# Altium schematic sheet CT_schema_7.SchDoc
size 218 x 258 mm
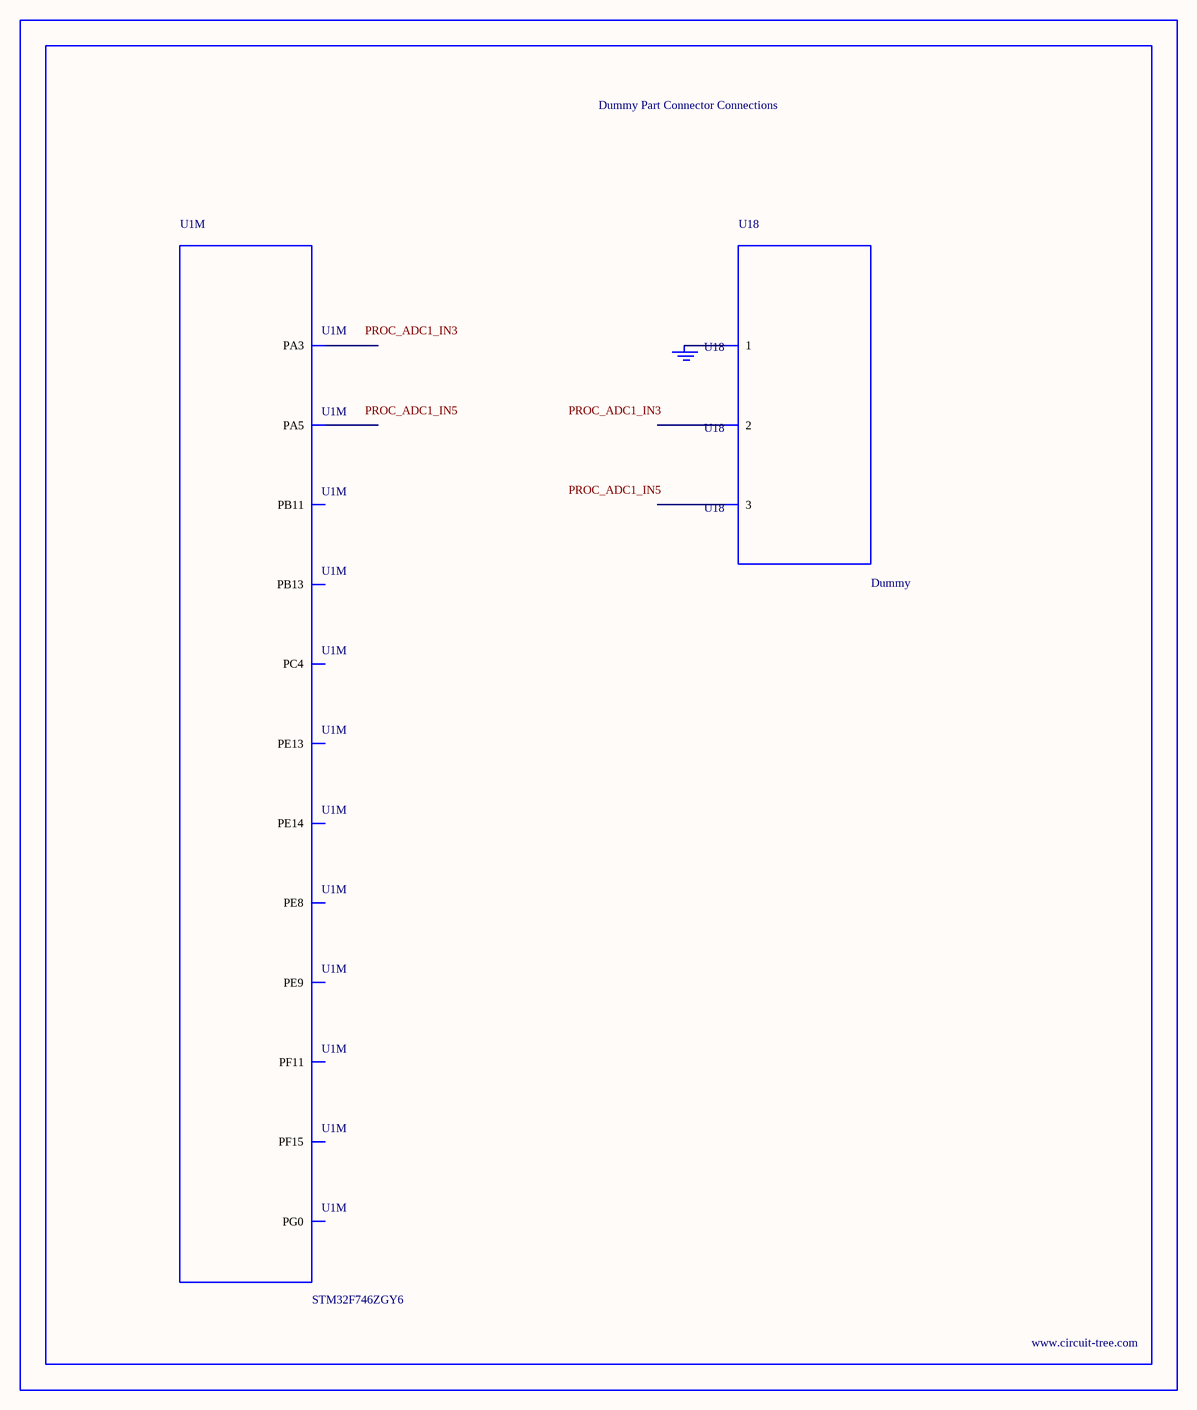
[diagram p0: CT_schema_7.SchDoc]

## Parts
BORDER6  (no value)
GND_INSTANCE_6_0  (no value)
U1  STM32F746ZGY6  [WLCSP143]  (part M of 13)
U18  Dummy  [DUMMY_PACKAGE_222]

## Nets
NetGND_INSTANCE_6_0_0: GND_INSTANCE_6_0.0(GND) U18.1

Not connected (* = marked no-connect by the designer): U1 M4(PE14) M5(PE8) M6(PF15) M7(PF11) M8(PC4) M9(PA5) M11(PA3) N1(PB13) N3(PB11) N4(PE13) N5(PE9) N6(PG0); U18 2 3

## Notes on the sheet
- Labels drawn without touching a wire or pin: PROC_ADC1_IN3, PROC_ADC1_IN5

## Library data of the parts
BORDER6 = BORDER_PAGE6
GND_INSTANCE_6_0 = GND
